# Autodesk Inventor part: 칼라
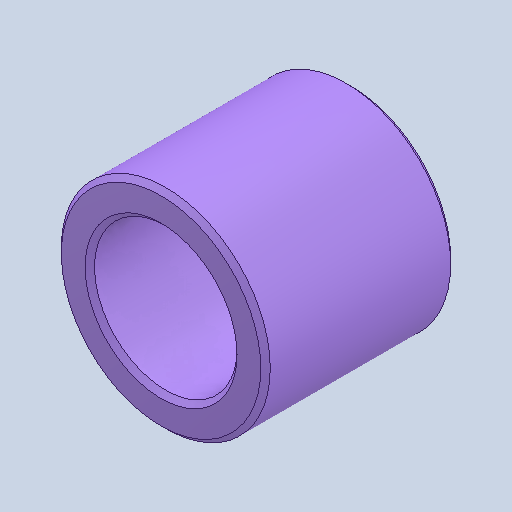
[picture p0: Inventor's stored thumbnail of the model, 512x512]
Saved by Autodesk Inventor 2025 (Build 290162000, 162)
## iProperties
Created: 2024-07
Part Number: 칼라
Material: 스테인리스강
Document SubType Name: Modeling
Designer: myung
Density: 8.08 g/cm^3
Appearance: 기본값
Author: jhkim
Sending System: Autodesk Inventor 2025
Preprocessor: ST-DEVELOPER v20
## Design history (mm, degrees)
feature "솔리드1"
node "솔리드2"
